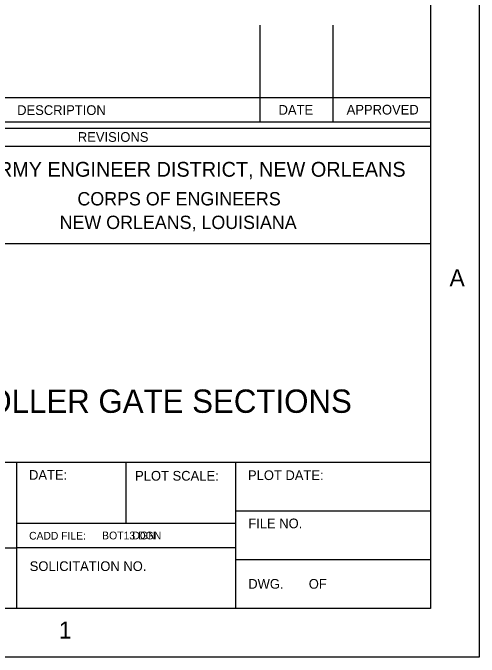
# Model space of a CAD drawing. Extents: x 4.9 to 31.6, y 3.9 to 22.6.
# Drawn here: x 28.38 to 31.574, y 3.926 to 8.343 of the extents above; entities that cross this region are included whole.
import ezdxf

# ---------------------------------------------------------------- set-up
doc = ezdxf.new("R2010")
doc.units = 0
doc.layers.add('Level 1', color=7, linetype='Continuous')
doc.layers.add('Level 2', color=7, linetype='Continuous')

msp = doc.modelspace()

# ---------------------------------------------------------------- linework, layer by layer
at = {"layer": 'Level 1'}
for p, q in [((30.0735, 7.5927), (30.0735, 8.2594)), ((30.5735, 7.5927), (30.5735, 8.2594)), ((31.2402, 7.7594), (26.9069, 7.7594)), ((31.2402, 7.5927), (26.9069, 7.5927)), ((31.2402, 7.551), (26.9069, 7.551)), ((31.2402, 7.426), (26.9069, 7.426)), ((31.2402, 6.7594), (26.9069, 6.7594)), ((31.2402, 5.2594), (26.9069, 5.2594)), ((28.4069, 4.2594), (28.4069, 5.2594)), ((29.1569, 4.8427), (29.1569, 5.2594)), ((29.9069, 4.2594), (29.9069, 5.2594)), ((31.2402, 4.926), (29.9069, 4.926)), ((29.9069, 4.8427), (28.4069, 4.8427)), ((26.9069, 4.676), (28.4069, 4.676)), ((29.9069, 4.676), (28.4069, 4.676)), ((31.2402, 4.5927), (29.9069, 4.5927))]:
    msp.add_line(p, q, dxfattribs=at)
for points in [[(4.9069, 22.5927), (31.5735, 22.5927), (31.5735, 3.926), (4.9069, 3.926)], [(5.9069, 22.2594), (31.2402, 22.2594), (31.2402, 4.2594), (5.9069, 4.2594)]]:
    msp.add_lwpolyline(points, close=True, dxfattribs=at)

# ---------------------------------------------------------------- texts
for s, height, p in [('DESCRIPTION', 0.066417, (28.4095, 7.6429)), ('DATE', 0.06642, (30.1999, 7.6445)), ('APPROVED', 0.06642, (30.6664, 7.6459)), ('REVISIONS', 0.06642, (28.8251, 7.4587)), ('U.S. ARMY ENGINEER DISTRICT, NEW ORLEANS', 0.101584, (27.8851, 7.2195)), ('CORPS OF ENGINEERS', 0.091425, (28.8222, 7.0226)), ('NEW ORLEANS, LOUISIANA', 0.091425, (28.7002, 6.861)), ('A', 0.1168, (31.371, 6.4683)), ('DATE:', 0.06642, (28.4908, 5.1419)), ('PLOT SCALE:', 0.066417, (29.2173, 5.136)), ('PLOT DATE:', 0.06642, (29.9905, 5.1399)), ('FILE NO.', 0.06642, (29.9924, 4.8094)), ('CADD FILE:', 0.05283, (28.4914, 4.7317)), ('SOLICITATION NO.', 0.066417, (28.4954, 4.5164)), ('DWG.       OF', 0.066417, (29.9924, 4.3951)), ('1', 0.1168, (28.6952, 4.0534))]:
    msp.add_text(s, height=height, dxfattribs=at).set_placement(p)
at = {"layer": 'Level 2'}
for s, height, p in [('BOTTOM ROLLER GATE SECTIONS', 0.16, (27.076, 5.6007)), ('BOT1.DGN', 0.05358, (28.991, 4.733)), ('BOT13.DGN', 0.05358, (28.991, 4.733))]:
    msp.add_text(s, height=height, dxfattribs=at).set_placement(p)

doc.saveas('drawing.dxf')
